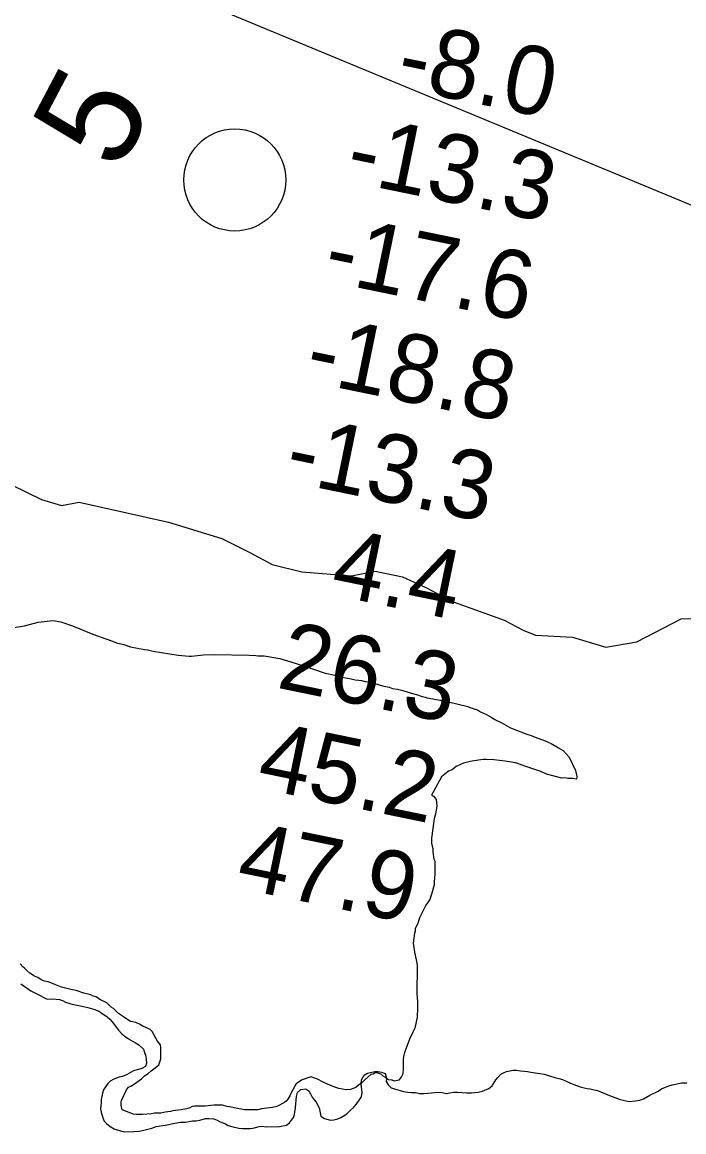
# Model space of a CAD drawing. Extents: x 3146026 to 3183936, y 897894 to 923344.
# Drawn here: x 3159445 to 3160093, y 910950 to 912037 of the extents above; entities that cross this region are included whole.
import ezdxf

# ---------------------------------------------------------------- set-up
doc = ezdxf.new("R2010")
doc.units = 0
for name, color, linetype in [('V-RIVR-EDGE', 7, 'Continuous'), ('V-RIVR-IDEN', 7, 'Continuous'), ('V-RIVR-MILE', 7, 'Continuous'), ('V-RIVR-RANG', 7, 'Continuous'), ('V-SITE-VEGE', 7, 'Continuous'), ('V-TOPO-BNDY', 7, 'Continuous'), ('V-TOPO-SHOR', 7, 'Continuous')]:
    doc.layers.add(name, color=color, linetype=linetype)

msp = doc.modelspace()

# ---------------------------------------------------------------- linework, layer by layer
at = {"layer": 'V-RIVR-EDGE'}
msp.add_lwpolyline([(3159434.856315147, 911583.1205031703), (3159463.7732496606, 911569.1681750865), (3159483.191575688, 911563.171234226), (3159500.6504746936, 911566.6974183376), (3159588.249380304, 911547.0476566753), (3159640.5603731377, 911531.0545068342), (3159667.890937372, 911517.1061013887), (3159689.675089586, 911505.5509805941), (3159719.00528788, 911498.3397455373), (3159767.3797748, 911494.2541793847), (3159790.7905043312, 911498.9554313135), (3159817.3484772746, 911493.3374311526), (3159840.3253491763, 911482.9691460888), (3159865.673931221, 911469.4222365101), (3159917.1858549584, 911451.051492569), (3159935.801189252, 911441.0905873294), (3159947.6871984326, 911436.3020567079), (3159984.168811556, 911434.228873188), (3160016.6658664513, 911424.6302374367), (3160047.2162428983, 911429.7104300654), (3160090.500730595, 911452.2093146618), (3160114.2982461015, 911452.9436602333)], dxfattribs=at)
at = {"layer": 'V-RIVR-MILE'}
msp.add_circle((3159653.125, 911882.233), 50.000000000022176, dxfattribs=at)
at = {"layer": 'V-SITE-VEGE'}
for points in [[(3159434.880000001, 911443.2729999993), (3159447.041000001, 911445.5159999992), (3159460.498000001, 911449.0689999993), (3159475.273000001, 911450.4529999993), (3159482.670000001, 911449.1919999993), (3159493.995000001, 911445.3419999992), (3159514.039000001, 911437.1929999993), (3159526.675000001, 911432.4799999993), (3159533.208000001, 911430.3439999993), (3159537.130000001, 911428.6259999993), (3159544.532000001, 911426.9279999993), (3159551.065000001, 911424.7919999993), (3159564.555000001, 911422.2589999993), (3159567.601000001, 911421.8409999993), (3159573.259000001, 911420.5689999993), (3159597.628000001, 911416.7899999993), (3159608.503000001, 911415.5449999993), (3159610.676000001, 911415.5599999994), (3159622.407000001, 911416.9279999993), (3159632.8400000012, 911417.4209999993), (3159667.191000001, 911416.7429999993), (3159673.714000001, 911416.3439999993), (3159675.889000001, 911415.9219999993), (3159681.975000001, 911415.9569999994), (3159697.206000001, 911413.4319999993), (3159712.449000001, 911408.7339999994), (3159729.436000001, 911403.1769999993), (3159741.633000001, 911398.8989999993), (3159748.160000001, 911397.6289999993), (3159759.916000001, 911394.6509999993), (3159767.313000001, 911393.3899999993), (3159771.231000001, 911392.5399999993), (3159777.322000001, 911391.7059999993), (3159780.806000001, 911390.8539999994), (3159783.853000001, 911390.4389999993), (3159792.559000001, 911388.3129999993)], [(3159792.559000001, 911388.3129999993), (3159797.7860000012, 911386.6029999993), (3159804.315000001, 911385.3329999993), (3159807.798000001, 911384.0509999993), (3159812.586000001, 911383.2069999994), (3159817.811000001, 911381.9309999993), (3159827.393000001, 911378.9409999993), (3159832.182000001, 911377.6629999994), (3159835.665000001, 911376.3789999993), (3159839.583000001, 911375.5309999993), (3159841.762000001, 911374.6749999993), (3159854.382000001, 911372.5719999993), (3159858.736000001, 911371.2919999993), (3159862.652000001, 911370.8779999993), (3159881.373000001, 911366.2009999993), (3159883.552000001, 911365.3429999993), (3159890.953000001, 911363.2109999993), (3159894.009000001, 911361.0519999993), (3159899.676000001, 911358.4759999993), (3159904.472000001, 911355.8929999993), (3159907.962000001, 911353.7409999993), (3159914.067000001, 911350.7299999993), (3159923.226000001, 911345.5649999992), (3159939.345000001, 911339.1319999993), (3159943.701000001, 911337.8519999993), (3159947.623000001, 911336.1359999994), (3159957.208000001, 911332.7119999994), (3159963.309000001, 911330.1349999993), (3159970.289000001, 911325.8279999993), (3159975.085000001, 911323.2459999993), (3159980.772000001, 911316.7559999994), (3159986.931000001, 911303.7489999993), (3159988.270000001, 911297.6679999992), (3159987.850000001, 911295.0569999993), (3159984.8030000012, 911295.9089999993), (3159979.584000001, 911295.8809999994), (3159976.539000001, 911296.2979999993), (3159973.496000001, 911296.2819999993), (3159958.691000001, 911300.1119999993), (3159953.028000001, 911302.6879999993), (3159937.346000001, 911307.8179999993), (3159929.505000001, 911310.8189999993), (3159924.282000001, 911311.6579999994), (3159918.189000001, 911312.9279999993), (3159906.878000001, 911314.1709999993), (3159899.485000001, 911314.5639999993), (3159896.442000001, 911314.5459999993), (3159892.100000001, 911313.6529999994), (3159883.847000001, 911312.3029999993), (3159877.334000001, 911310.9619999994), (3159874.297000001, 911309.6409999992), (3159869.961000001, 911307.4439999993), (3159866.066000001, 911304.3799999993), (3159862.594000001, 911303.0549999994), (3159859.133000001, 911299.9929999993), (3159855.670000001, 911297.3629999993), (3159845.770000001, 911279.4839999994), (3159847.949000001, 911278.6259999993), (3159850.577000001, 911275.1609999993), (3159851.046000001, 911269.0799999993), (3159849.7860000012, 911260.8129999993), (3159848.508000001, 911256.4569999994), (3159848.086000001, 911253.8449999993), (3159846.006000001, 911237.3139999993), (3159846.032000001, 911232.5319999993), (3159846.485000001, 911229.4909999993), (3159847.366000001, 911227.3219999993), (3159847.384000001, 911223.8439999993), (3159848.293000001, 911216.8909999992), (3159849.176000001, 911214.7239999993), (3159849.252000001, 911201.2469999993), (3159848.828000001, 911199.0719999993), (3159848.422000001, 911193.8509999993), (3159848.435000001, 911191.6779999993), (3159846.307000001, 911183.4019999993), (3159844.167000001, 911177.3069999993), (3159840.2860000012, 911171.6319999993), (3159834.267000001, 911159.4259999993), (3159832.559000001, 911153.7659999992), (3159829.976000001, 911148.9669999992), (3159829.992000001, 911146.3599999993), (3159829.134000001, 911144.1809999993), (3159827.883000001, 911134.6109999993), (3159829.239000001, 911125.4869999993), (3159831.018000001, 911118.1059999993), (3159831.917000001, 911112.8939999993), (3159831.983000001, 911100.7199999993), (3159831.578000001, 911095.9359999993), (3159831.637000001, 911085.0679999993), (3159832.118000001, 911076.8099999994), (3159832.165000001, 911068.5499999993), (3159831.752000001, 911064.6349999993), (3159831.766000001, 911062.0279999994), (3159829.652000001, 911051.1469999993), (3159827.502000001, 911047.2209999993), (3159826.6440000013, 911045.0409999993), (3159824.922000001, 911041.9899999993), (3159819.353000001, 911027.1769999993), (3159818.931000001, 911024.5659999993), (3159818.081000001, 911021.0839999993), (3159818.134000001, 911011.5199999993)], [(3159494.243000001, 911088.8399999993), (3159491.198000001, 911089.2579999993), (3159488.585000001, 911090.1139999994), (3159483.360000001, 911091.3879999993), (3159476.825000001, 911093.9599999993), (3159472.901000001, 911095.6779999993), (3159470.292000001, 911096.5319999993), (3159466.806000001, 911097.3819999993), (3159463.320000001, 911098.6659999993), (3159460.265000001, 911100.8249999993), (3159456.779000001, 911102.1089999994), (3159452.415000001, 911105.1279999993), (3159449.355000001, 911107.7179999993), (3159447.172000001, 911109.8809999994), (3159445.425000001, 911111.1749999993), (3159442.800000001, 911114.2039999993)], [(3159818.134000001, 911011.5199999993), (3159817.729000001, 911006.3019999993), (3159816.439000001, 911003.6819999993), (3159813.850000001, 911000.1899999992), (3159809.508000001, 910999.2969999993), (3159807.329000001, 911000.1549999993), (3159803.413000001, 911000.5669999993), (3159800.794000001, 911002.7279999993), (3159798.613000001, 911004.0179999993), (3159796.864000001, 911005.7489999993), (3159792.942000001, 911007.4649999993), (3159790.767000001, 911007.4519999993), (3159788.600000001, 911006.1379999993), (3159786.429000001, 911005.6889999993), (3159780.806000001, 911000.8759999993), (3159777.346000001, 910997.3779999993), (3159774.315000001, 910995.1869999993), (3159771.719000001, 910993.0019999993), (3159766.511000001, 910991.2319999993), (3159762.167000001, 910990.7739999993), (3159755.204000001, 910992.0389999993), (3159752.156000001, 910992.8909999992), (3159744.748000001, 910995.8919999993), (3159739.082000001, 910998.4699999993), (3159734.285000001, 911001.0499999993), (3159727.748000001, 911003.6249999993), (3159719.071000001, 911000.5319999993), (3159715.605000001, 910998.3389999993), (3159713.441000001, 910996.5879999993), (3159709.136000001, 910989.1719999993), (3159706.985000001, 910984.8139999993), (3159705.263000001, 910981.7599999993), (3159703.537000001, 910979.5769999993), (3159701.806000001, 910978.2639999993), (3159694.435000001, 910974.3099999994), (3159690.093000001, 910973.4169999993), (3159681.836000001, 910972.4989999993), (3159679.233000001, 910972.0509999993), (3159675.760000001, 910971.1619999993), (3159663.150000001, 910971.0919999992), (3159655.753000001, 910972.3559999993), (3159647.917000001, 910974.0499999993), (3159645.306000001, 910974.4709999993), (3159640.952000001, 910975.7509999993), (3159632.692000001, 910975.7019999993), (3159624.002000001, 910974.7869999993), (3159613.568000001, 910974.7299999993), (3159611.397000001, 910974.2809999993), (3159609.230000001, 910972.9639999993), (3159605.757000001, 910972.0769999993), (3159600.545000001, 910971.1779999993), (3159592.289000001, 910970.2629999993), (3159590.120000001, 910969.3799999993), (3159584.906000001, 910968.9169999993), (3159580.564000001, 910968.0219999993), (3159574.478000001, 910967.9899999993), (3159571.439000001, 910967.1029999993), (3159562.747000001, 910966.6189999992), (3159556.660000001, 910966.5869999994), (3159554.049000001, 910967.0069999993), (3159551.436000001, 910967.8629999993), (3159542.721000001, 910971.2889999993), (3159541.829000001, 910975.6329999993), (3159541.812000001, 910978.2419999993), (3159542.236000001, 910980.4189999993), (3159546.961000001, 910990.8779999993), (3159549.119000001, 910993.4989999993), (3159551.288000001, 910994.3799999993), (3159554.753000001, 910996.5739999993), (3159561.684000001, 911001.3949999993), (3159564.709000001, 911004.4539999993), (3159568.174000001, 911006.6479999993), (3159571.205000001, 911009.2729999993), (3159575.100000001, 911012.3389999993), (3159578.561000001, 911015.4009999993), (3159580.704000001, 911021.0659999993), (3159580.652000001, 911030.1929999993), (3159580.640000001, 911032.3679999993), (3159580.192000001, 911034.9739999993), (3159577.562000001, 911038.4389999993), (3159572.293000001, 911047.9719999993), (3159570.109000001, 911049.7009999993), (3159567.056000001, 911051.4209999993), (3159562.700000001, 911053.1369999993), (3159560.517000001, 911054.8639999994), (3159556.158000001, 911056.5759999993), (3159553.111000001, 911057.4319999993), (3159550.934000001, 911057.8539999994), (3159549.191000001, 911058.7139999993), (3159543.954000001, 911062.1629999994), (3159539.154000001, 911065.6119999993), (3159534.343000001, 911070.3689999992), (3159532.164000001, 911071.6609999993), (3159527.792000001, 911075.9849999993), (3159521.688000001, 911078.9929999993), (3159516.888000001, 911082.0099999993), (3159514.279000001, 911082.4339999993), (3159512.098000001, 911083.7219999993), (3159505.130000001, 911085.4239999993), (3159497.727000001, 911087.9899999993), (3159494.243000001, 911088.8399999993)]]:
    msp.add_lwpolyline(points, dxfattribs=at)
at = {"layer": 'V-TOPO-BNDY'}
msp.add_lwpolyline([(3162288.0485607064, 912035.1193577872), (3162225.514274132, 912006.2645998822), (3162087.305464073, 911943.1889477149), (3161778.1195046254, 911799.8221818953), (3161261.5298716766, 911668.3447235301), (3160960.59504134, 911648.5365415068), (3160815.943860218, 911663.2946838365), (3160685.64507727, 911676.589578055), (3160605.8988812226, 911699.9980547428), (3160140.638647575, 911840.9391507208), (3159445.187113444, 912129.3016423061), (3158861.879770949, 912432.7324246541), (3158245.4111681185, 912823.6388573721), (3157767.9295387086, 913092.6725836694), (3157135.275562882, 913454.6088522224), (3156545.813290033, 913785.7040784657)], dxfattribs=at)
at = {"layer": 'V-TOPO-SHOR'}
for points in [[(3159443.543000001, 911094.7049999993), (3159453.412000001, 911087.7959999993), (3159459.165000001, 911084.7539999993), (3159469.438000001, 911079.6919999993), (3159474.967000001, 911079.9269999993), (3159481.320000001, 911079.3479999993), (3159484.196000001, 911078.1329999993), (3159487.278000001, 911076.5129999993), (3159492.408000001, 911074.9009999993), (3159496.7150000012, 911073.9019999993), (3159500.201000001, 911073.5129999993), (3159509.022000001, 911071.5119999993), (3159515.997000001, 911069.2979999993), (3159519.899000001, 911067.6799999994), (3159522.778000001, 911065.8529999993), (3159527.919000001, 911062.1929999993), (3159530.595000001, 911059.9549999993), (3159532.862000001, 911057.3049999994), (3159539.0530000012, 911049.3499999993), (3159542.556000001, 911045.6829999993), (3159545.849000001, 911043.0359999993), (3159549.140000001, 911040.8019999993), (3159555.921000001, 911036.9479999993), (3159559.212000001, 911034.7129999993), (3159563.537000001, 911030.4349999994), (3159564.785000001, 911027.1639999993), (3159565.827000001, 911023.6869999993), (3159566.255000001, 911020.6169999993), (3159566.685000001, 911016.7279999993), (3159565.680000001, 911013.6479999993), (3159562.208000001, 911011.5789999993), (3159558.731000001, 911010.5369999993), (3159553.820000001, 911009.4839999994), (3159547.084000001, 911005.3489999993), (3159543.201000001, 911003.6899999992), (3159539.926000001, 911003.0569999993), (3159534.609000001, 911001.1839999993), (3159531.140000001, 910999.1149999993), (3159528.693000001, 910996.8499999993), (3159524.629000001, 910990.6789999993), (3159523.419000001, 910987.3959999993), (3159522.225000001, 910981.2419999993), (3159522.241000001, 910978.1699999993), (3159521.660000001, 910972.2269999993), (3159522.293000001, 910968.9519999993), (3159523.964000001, 910963.4309999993), (3159525.209000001, 910960.1599999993), (3159527.271000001, 910957.9179999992), (3159531.181000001, 910954.8659999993), (3159535.084000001, 910952.6359999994), (3159542.2690000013, 910950.2169999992), (3159545.550000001, 910949.6189999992), (3159554.356000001, 910949.8749999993), (3159559.067000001, 910950.3089999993), (3159562.751000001, 910950.9439999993), (3159571.957000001, 910953.2499999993), (3159576.044000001, 910954.7059999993), (3159585.052000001, 910956.1909999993), (3159594.259000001, 910958.0849999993), (3159599.990000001, 910958.9369999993), (3159604.700000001, 910959.1689999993), (3159611.864000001, 910960.2339999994), (3159615.346000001, 910960.4569999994), (3159619.030000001, 910961.0919999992), (3159624.5530000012, 910962.5559999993), (3159627.828000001, 910962.7789999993), (3159632.545000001, 910962.1919999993), (3159636.034000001, 910960.9809999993), (3159638.912000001, 910959.3589999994), (3159644.042000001, 910957.5449999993), (3159646.7150000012, 910955.9209999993), (3159650.409000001, 910954.7099999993), (3159656.971000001, 910953.3139999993), (3159660.866000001, 910952.9269999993), (3159668.653000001, 910952.7649999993), (3159672.540000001, 910953.4019999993), (3159675.608000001, 910954.4419999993), (3159679.088000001, 910955.0769999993), (3159684.416000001, 910954.4909999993), (3159697.116000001, 910954.7679999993), (3159703.664000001, 910956.0309999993), (3159706.725000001, 910958.3029999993), (3159710.588000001, 910963.6519999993), (3159711.595000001, 910966.5229999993), (3159712.787000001, 910973.2919999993), (3159713.750000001, 910984.3589999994)], [(3159713.750000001, 910984.3589999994), (3159714.547000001, 910988.2569999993), (3159718.014000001, 910991.1419999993), (3159722.722000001, 910991.7829999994), (3159725.602000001, 910989.7519999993), (3159727.461000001, 910986.6899999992), (3159728.913000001, 910983.6239999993), (3159730.773000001, 910980.9719999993), (3159732.833000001, 910978.5239999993), (3159735.731000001, 910973.2139999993), (3159737.417000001, 910965.0279999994), (3159740.9110000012, 910962.7959999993), (3159746.862000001, 910960.9849999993), (3159750.342000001, 910961.4129999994), (3159754.229000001, 910962.4599999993), (3159757.0900000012, 910963.7049999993), (3159760.969000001, 910965.9799999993), (3159763.623000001, 910967.8379999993), (3159765.861000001, 910970.3099999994), (3159769.736000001, 910973.6089999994), (3159771.975000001, 910976.2839999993), (3159777.258000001, 910983.8919999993), (3159778.0530000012, 910988.1989999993), (3159776.984000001, 910996.1819999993), (3159777.369000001, 911000.4869999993), (3159779.804000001, 911005.0069999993), (3159783.275000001, 911007.0759999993), (3159790.2320000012, 911008.5479999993), (3159793.302000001, 911008.7709999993), (3159796.995000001, 911008.1769999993), (3159800.485000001, 911006.7619999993), (3159801.945000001, 911002.2629999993), (3159801.554000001, 910998.7769999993), (3159803.415000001, 910995.5109999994), (3159806.504000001, 910992.8649999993), (3159809.787000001, 910991.6539999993), (3159818.405000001, 910989.2439999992), (3159822.507000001, 910988.4469999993), (3159826.400000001, 910988.0599999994), (3159830.293000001, 910988.0799999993), (3159834.191000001, 910987.2839999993), (3159838.494000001, 910987.1039999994), (3159842.180000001, 910987.3289999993), (3159845.862000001, 910987.9639999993), (3159852.211000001, 910988.4079999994), (3159856.514000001, 910988.2279999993), (3159860.430000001, 910987.0769999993), (3159860.526000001, 910987.0479999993), (3159863.891000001, 910987.8589999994), (3159867.370000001, 910988.4919999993), (3159871.466000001, 910988.5149999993), (3159880.691000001, 910987.7469999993), (3159885.196000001, 910987.7709999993), (3159891.545000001, 910988.4219999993), (3159896.044000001, 910989.4709999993), (3159901.969000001, 910992.1679999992), (3159905.234000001, 910994.6439999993), (3159909.094000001, 911000.4009999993), (3159910.925000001, 911002.8689999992), (3159913.981000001, 911005.9589999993), (3159916.635000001, 911007.4089999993), (3159919.496000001, 911008.6549999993), (3159925.839000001, 911010.1229999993), (3159929.320000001, 911010.1439999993), (3159933.218000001, 911009.3449999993), (3159936.701000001, 911009.1609999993), (3159939.9820000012, 911008.5629999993), (3159943.263000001, 911008.1709999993), (3159956.182000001, 911005.9899999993), (3159959.668000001, 911005.1909999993), (3159967.671000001, 911002.5719999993), (3159970.747000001, 911001.9739999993), (3159974.235000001, 911000.9709999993), (3159982.247000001, 910997.1219999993), (3159985.325000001, 910996.1149999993), (3159991.690000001, 910993.6919999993), (3159995.383000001, 910992.6879999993), (3159998.459000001, 910992.0899999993), (3160001.535000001, 910991.6969999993), (3160005.432000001, 910990.6959999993), (3160008.508000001, 910990.0979999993), (3160020.417000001, 910985.0429999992), (3160030.682000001, 910981.2069999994), (3160039.501000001, 910979.4129999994), (3160045.850000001, 910979.8599999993), (3160050.146000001, 910980.7019999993), (3160053.622000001, 910981.9509999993), (3160059.952000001, 910985.4669999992), (3160067.921000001, 910989.4059999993), (3160071.390000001, 910991.6789999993), (3160075.273000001, 910993.3379999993), (3160078.339000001, 910994.5849999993), (3160081.612000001, 910995.6269999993), (3160091.229000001, 910997.5239999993), (3160096.1440000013, 910997.7569999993)]]:
    msp.add_lwpolyline(points, dxfattribs=at)

# ---------------------------------------------------------------- texts
at = {"layer": 'V-RIVR-IDEN'}
msp.add_text('5', height=99.99980199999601, rotation=62.24436140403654, dxfattribs=at).set_placement((3159539.2226505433, 911888.3525336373))
at = {"layer": 'V-RIVR-RANG'}
for s, p in [('-8.0', (3159809.4530702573, 911973.6233892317)), ('-13.3', (3159759.845311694, 911881.7332571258)), ('-17.6', (3159738.141708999, 911784.1042229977)), ('-18.8', (3159720.055311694, 911685.7312571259)), ('-13.3', (3159700.160311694, 911587.7302571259)), ('4.4', (3159745.3750087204, 911476.3384857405)), ('26.3', (3159692.925160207, 911385.0328714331)), ('45.2', (3159673.030160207, 911287.031871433)), ('47.9', (3159652.8767883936, 911189.0840094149))]:
    msp.add_text(s, height=67, rotation=348.3783257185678, dxfattribs=at).set_placement(p)

doc.saveas('drawing.dxf')
